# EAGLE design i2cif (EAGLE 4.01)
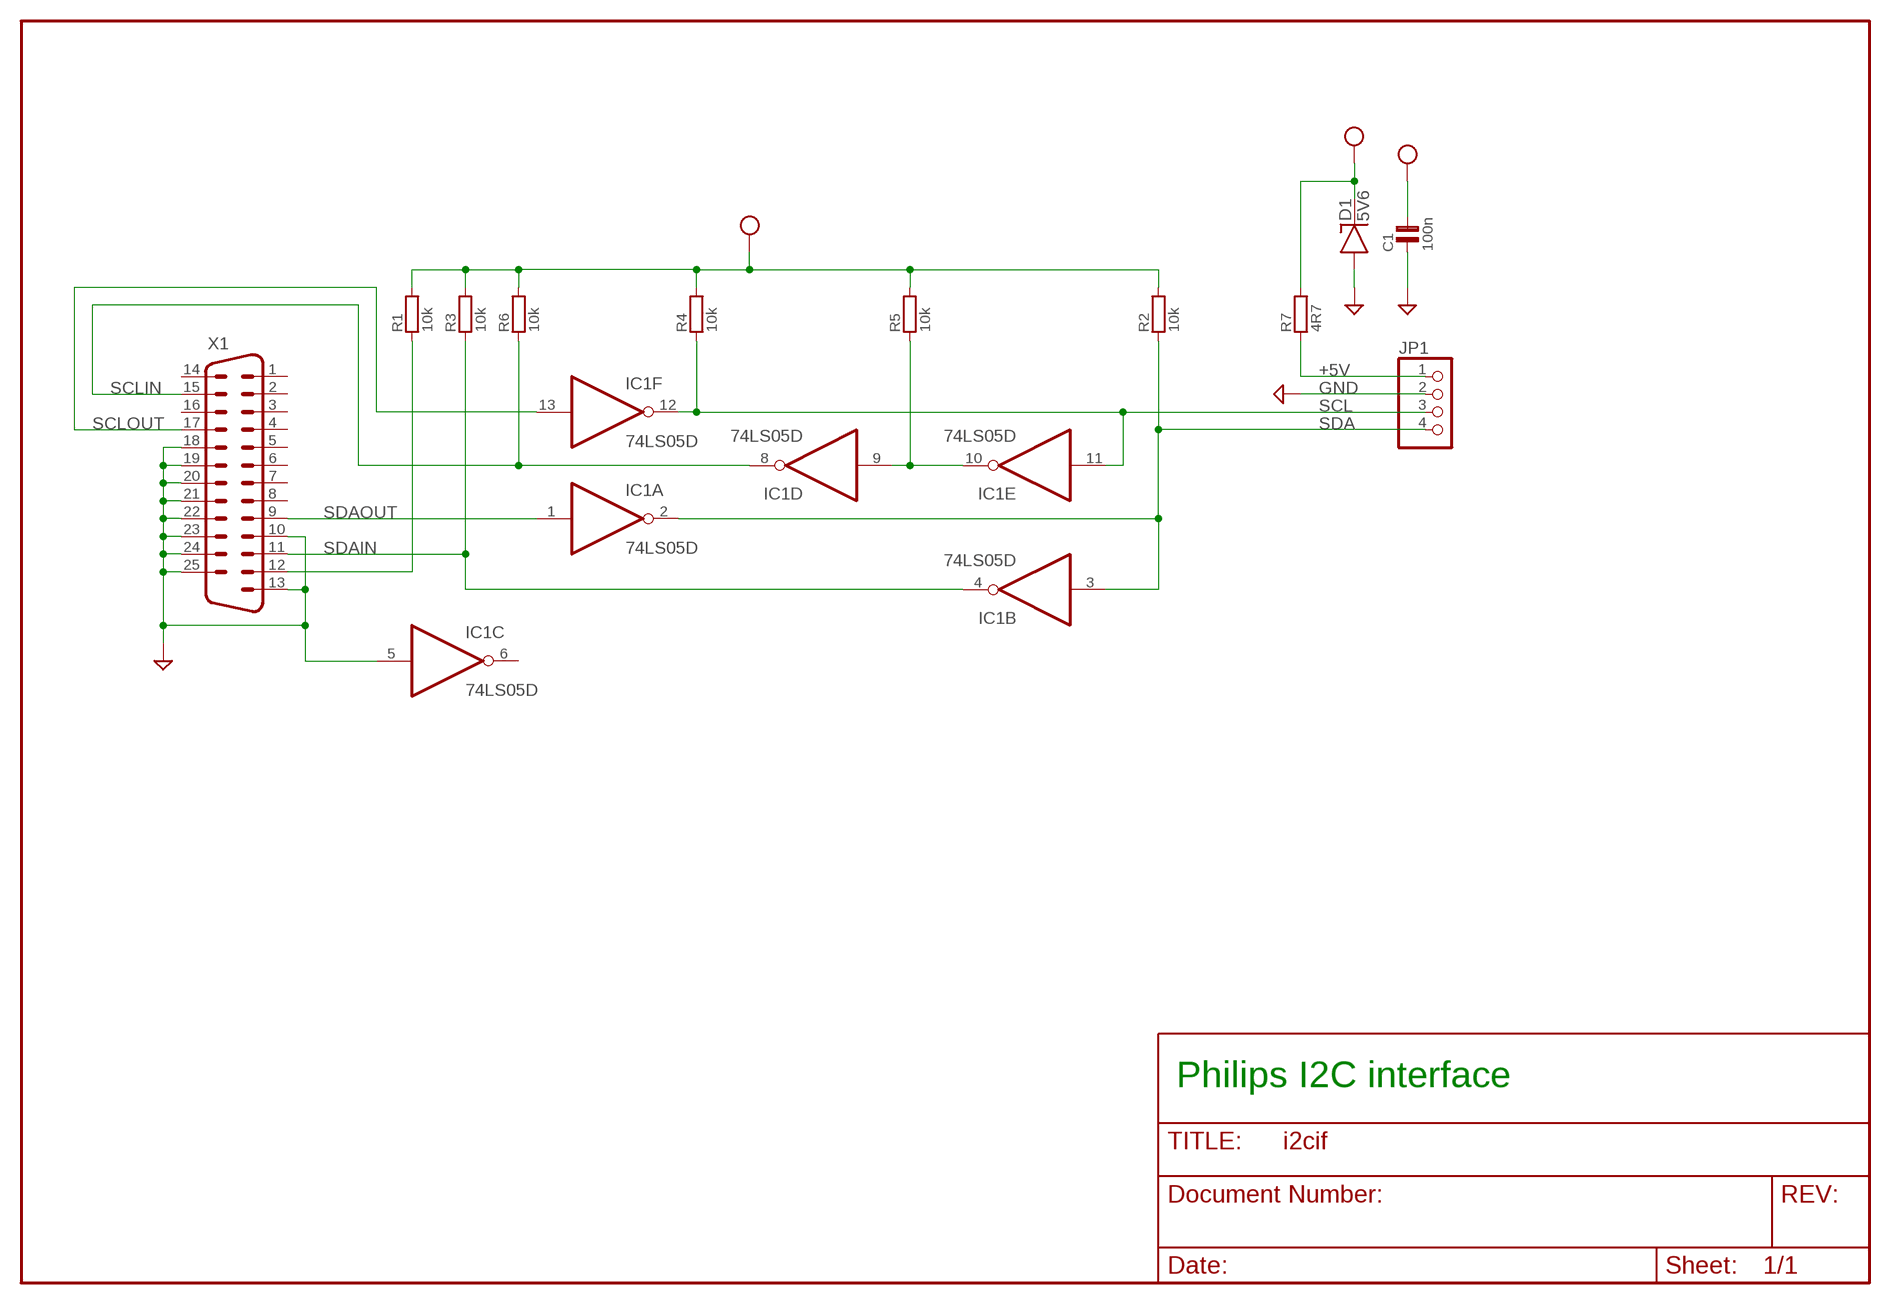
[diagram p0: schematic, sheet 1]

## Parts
C1  100n  C1206  [1206]
D1  5V6  BZV55  [SOD80]
IC1  74LS05D  [SO14]
JP1  PINHD-1X4  [1X04]
R1  10k  R1206  [1206]
R2  10k  R1206  [1206]
R3  10k  R1206  [1206]
R4  10k  R1206  [1206]
R5  10k  R1206  [1206]
R6  10k  R1206  [1206]
R7  4R7  R1206  [1206]
X1  M25D  [M25D]

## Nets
+5V: JP1.1 R7.1
GND: C1.1 D1.1(A) IC1.5(C:I) JP1.2 X1.10 X1.13 X1.18 X1.19 X1.20 X1.21 X1.22 X1.23 X1.24 X1.25
N$2: R1.1 X1.12
N$3: IC1.9(D:I) IC1.10(E:O) R5.1
SCL: IC1.11(E:I) IC1.12(F:O) JP1.3 R4.1
SCLIN: IC1.8(D:O) R6.1 X1.15
SCLOUT: IC1.13(F:I) X1.17
SDA: IC1.2(A:O) IC1.3(B:I) JP1.4 R2.1
SDAIN: IC1.4(B:O) R3.1 X1.11
SDAOUT: IC1.1(A:I) X1.9
VCC: C1.2 D1.2(K) R1.2 R2.2 R3.2 R4.2 R5.2 R6.2 R7.2
Unconnected: IC1.6(C:O) X1.1 X1.2 X1.3 X1.4 X1.5 X1.6 X1.7 X1.8 X1.14 X1.16

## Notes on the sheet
- Philips I2C interface

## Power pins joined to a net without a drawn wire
GND: IC1.7(P:GND)
VCC: IC1.14(P:VCC)

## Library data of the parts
C1 = weini:C1206
D1 = weini:BZV55
IC1 = 74xx-eu:74*05: Hex INVERTER, open collector
JP1 = pinhead:PINHD-1X4: PIN HEADER
R1-R7 = weini:R1206
X1 = con-subd:M25D: HARTING SUB-D

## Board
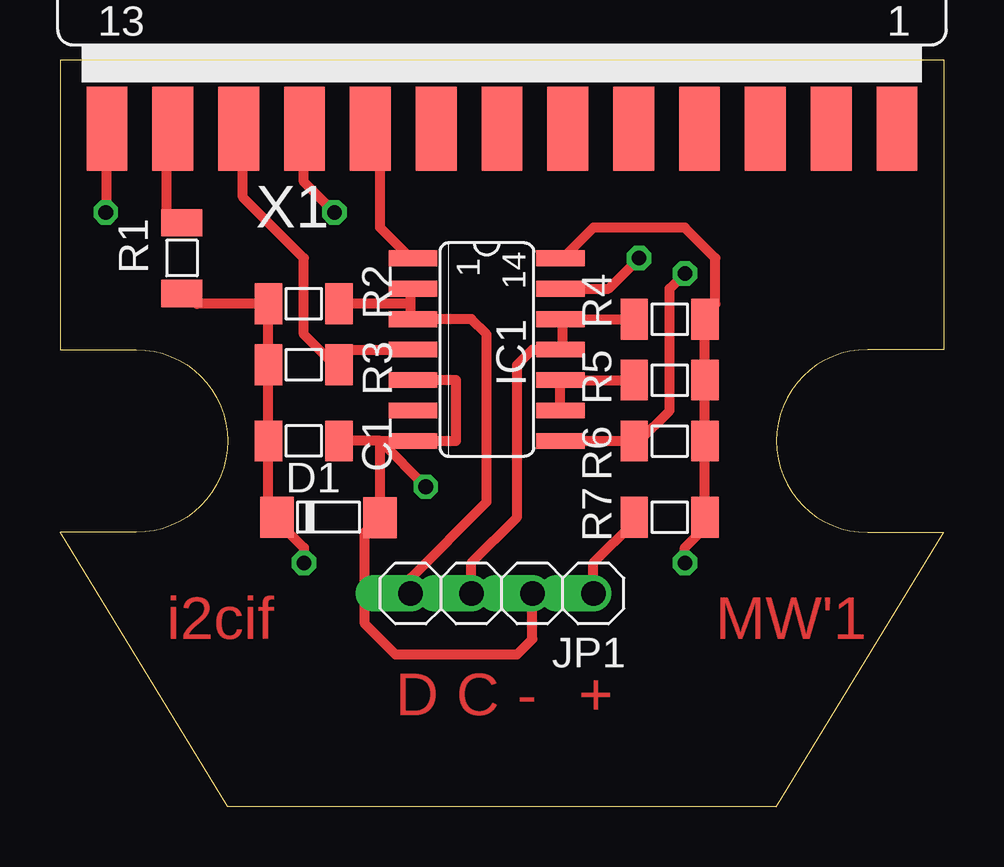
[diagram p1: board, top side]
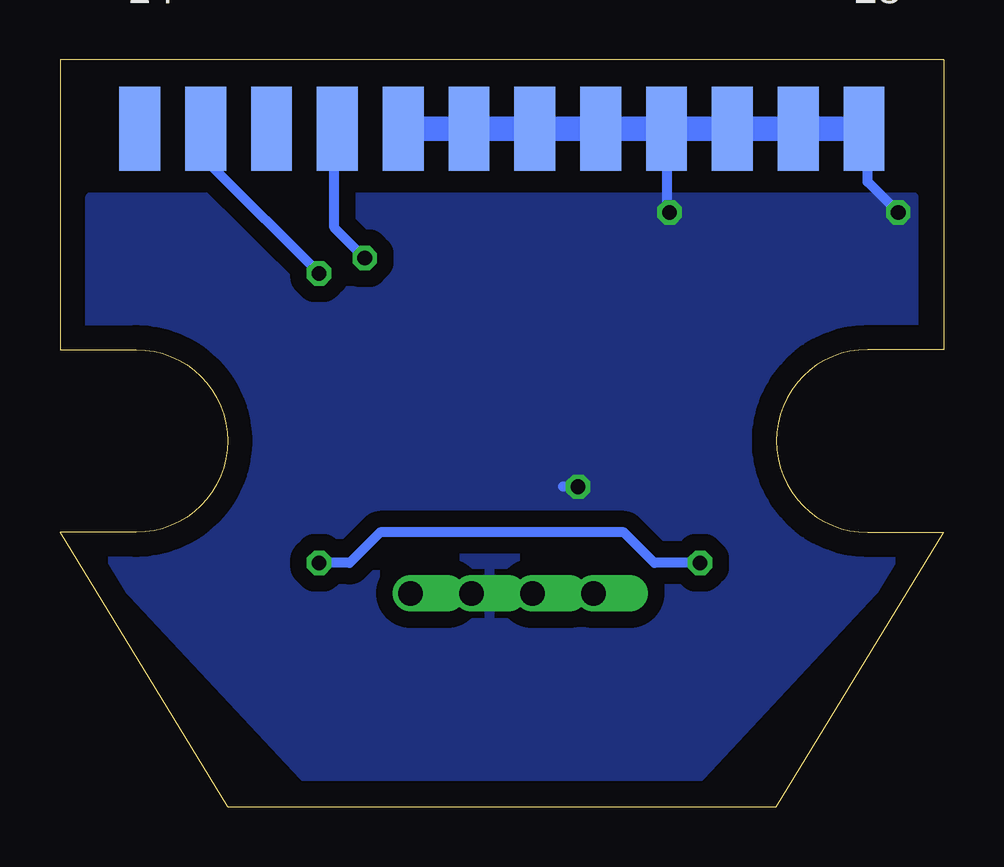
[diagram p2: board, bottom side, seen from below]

Size 36.83 x 31.11 mm. Coordinates in mm from the lower left corner, seen from the top.
Outline: 0,31.11 36.83,31.11 36.83,19.05 33.66,19.05 arc180 33.66,11.43 36.83,11.43 29.84,0 6.98,0 0,11.43 3.17,11.43 arc180 3.17,19.05 0,19.05 0,31.11
Copper layers used: Top, Bottom

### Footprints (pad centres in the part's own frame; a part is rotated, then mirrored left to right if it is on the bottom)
1206 = smd 1.143 x 1.702: 1 -1.473,0; 2 1.473,0
SOD80 = smd 1.397 x 1.702: 1 1.905,-0.025; 2 -2.388,0
SO14 = smd 0.66 x 2.032: 1 -3.81,-3.073; 2 -2.54,-3.073; 3 -1.27,-3.073; 4 0,-3.073; 5 1.27,-3.073; 6 2.54,-3.073; 7 3.81,-3.073; 8 3.81,3.073; 9 2.54,3.073; 10 1.27,3.073; 11 0,3.073; 12 -1.27,3.073; 13 -2.54,3.073; 14 -3.81,3.073
1X04 = drill 1.016 offset: 1 -3.81,0; 2 -1.27,0; 3 1.27,0; 4 3.81,0
M25D = smd 1.7 x 3.5: 1 16.459,-6.045; 2 13.716,-6.045; 3 10.973,-6.045; 4 8.23,-6.045; 5 5.486,-6.045; 6 2.743,-6.045; 7 0,-6.045; 8 -2.743,-6.045; 9 -5.486,-6.045; 10 -8.23,-6.045; 11 -10.973,-6.045; 12 -13.716,-6.045; 13 -16.459,-6.045 | smd 1.7 x 3.5 bottom: 14 15.088,-6.045; 15 12.344,-6.045; 16 9.601,-6.045; 17 6.858,-6.045; 18 4.115,-6.045; 19 1.372,-6.045; 20 -1.372,-6.045; 21 -4.115,-6.045; 22 -6.858,-6.045; 23 -9.601,-6.045; 24 -12.344,-6.045; 25 -15.088,-6.045

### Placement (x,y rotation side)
C1  10.16,15.24 180 top
D1  11.43,12.06 0 top
IC1  17.78,19.05 270 top
JP1  18.41,8.89 180 top
R1  5.08,22.86 270 top
R2  10.16,20.95 180 top
R3  10.16,18.41 180 top
R4  25.4,20.32 0 top
R5  25.4,17.78 0 top
R6  25.4,15.24 0 top
R7  25.4,12.06 0 top
X1  18.41,34.29 0 top

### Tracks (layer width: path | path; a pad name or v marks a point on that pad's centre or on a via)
+5V
  Top 0.406: R7.1 23.93,11.86 22.22,10.16 JP1.1
GND  (via drill 0.61)
  Top 0.406: 14.6,17.78 IC1.5 16.51,17.78 16.51,15.24 IC1.7 13.33,15.24 | 13.33,12.06 13.33,15.24 | JP1.2 19.68,6.99 19.05,6.35 13.97,6.35 12.7,7.62 12.7,11.43 13.33,12.06 | 13.33,12.06 D1.1 | 10.16,27.3 10.16,26.04 v11.43,24.77 11.56,24.89 | 10.16,27.3 10.16,27.94 | X1.10 10.18,28.55 10.16,28.57 10.16,27.3 | X1.13 1.96,24.82 v1.9,24.77 | 13.33,15.24 C1.1 | 13.33,15.24 v15.24,13.34
  Bottom 0.406: 5.38,28.25 5.41,28.25 5.71,27.94 6.02,28.25 6.04,28.25 | 6.65,28.25 6.35,27.94 6.07,28.22 X1.24 | X1.22 11.56,24.89 v11.43,24.77 | 11.12,28.25 11.43,27.94 11.56,28.07 | v1.9,24.77 3.17,26.04 3.17,27.94 3.33,28.09 X1.25 | v15.24,13.34 15.88,13.34
  Bottom 1.016: 6.04,28.25 X1.24 | X1.25 5.38,28.25 5.71,28.57 | 11.56,28.07 X1.22 14.27,28.25 14.3,28.27 | 11.12,28.25 X1.23 6.65,28.25 | 14.3,28.27 14.6,28.57 | 14.3,28.27 X1.21 16.81,28.25 17.04,28.47 | 17.04,28.47 17.14,28.57 | 17.04,28.47 X1.20 19.36,28.25 19.68,28.57 19.79,28.47 X1.19 21.89,28.25 22.22,28.57 22.53,28.27 X1.18
  pour Bottom (isolate 0.69): 1.27,25.4 1.27,10.79 10.16,1.27 26.67,1.27 35.56,10.79 35.56,25.4
N$2
  Top 0.406: R1.1 4.88,24.33 4.44,24.77 4.44,27.94 4.7,28.19 X1.12
N$3
  Top 0.406: R5.1 IC1.10 20.85,16.61 20.95,16.51 IC1.9
SCL
  Top 0.406: 20.95,20.32 20.95,19.05 IC1.11 19.68,19.05 19.05,18.41 19.05,12.06 17.14,10.16 JP1.3 | 20.95,20.32 IC1.12 | 20.95,20.32 R4.1
SCLIN  (via drill 0.61)
  Top 0.406: v26.04,22.23 25.4,21.59 25.4,16.51 24.13,15.24 R6.1 IC1.8
  Bottom 0.406: v26.04,22.23 30.48,26.67 30.48,27.94 30.76,28.22 X1.15
SCLOUT  (via drill 0.61)
  Top 0.406: IC1.13 22.86,21.59 v24.13,22.86
  Bottom 0.406: v24.13,22.86 25.4,24.13 25.4,27.94 25.27,28.07 X1.17
SDA
  Top 0.406: IC1.2 14.6,21.59 14.6,20.95 | 14.6,20.32 14.6,20.95 | 14.6,20.95 R2.1 | JP1.4 14.6,9.53 17.78,12.7 17.78,19.68 17.14,20.32 14.6,20.32 | 14.6,20.32 IC1.3
SDAIN
  Top 0.406: IC1.4 12.06,19.05 11.63,18.62 R3.1 11.43,18.41 10.16,19.68 10.16,22.86 7.62,25.4 7.62,27.94 7.44,28.12 X1.11
SDAOUT
  Top 0.406: IC1.1 14.6,22.86 13.33,24.13 13.33,27.94 13.03,28.25 X1.9
VCC  (via drill 0.61)
  Top 0.406: 26.67,12.06 R7.2 | 26.67,12.06 26.87,12.27 R6.2 26.67,15.24 26.87,15.44 R5.2 26.67,17.78 26.87,17.98 R4.2 26.67,20.32 27.3,20.95 27.3,22.86 26.04,24.13 22.22,24.13 20.95,22.86 IC1.14 | R1.2 5.08,21.59 5.71,20.95 R2.2 8.89,20.95 8.69,20.75 R3.2 8.89,18.41 8.69,18.21 C1.2 8.69,12.27 8.89,12.06 | D1.2 8.89,12.06 | v10.16,10.16 10.16,10.79 8.89,12.06 | v26.04,10.16 26.04,10.79 26.67,11.43 26.67,12.06
  Bottom 0.406: v10.16,10.16 12.06,10.16 13.33,11.43 23.49,11.43 24.77,10.16 v26.04,10.16

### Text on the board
Top: MW'1 | D | C | - | +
